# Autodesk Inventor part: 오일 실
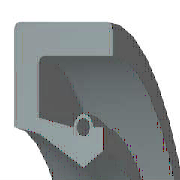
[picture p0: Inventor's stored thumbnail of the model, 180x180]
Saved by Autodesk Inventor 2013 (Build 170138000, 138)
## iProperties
IsCustomPart: 1
Created: 2015-10
Part Number: 오일 실
Material: 고무
Description: 오일-실
Document SubType Name: Modeling
Standard: KS B 2804
Designer: mdu
Standards Organization: KS
Language: ko-KR
Size Designation: S - 25 38 8
Categories: <MemberInstance><Categories><Category DisplayName="샤프트 부품" InternalName="7f7aeb1f-a693-4053-b835-cee3144e0d98" Mnemonic="SHFT"><Category DisplayName="실링" Intern
Density: 0.93 g/cm^3
Author: mdu
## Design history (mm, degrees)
revolve "본체" stored, may be unused: angle "d17" = 90 deg
revolve "스프링1" stored, may be unused: angle "d18" = 90 deg
body "Solid1"
sketch "스케치1"
  geometry: L1 (0, 19)-(8, 19); L2 (8, 19)-(8, 17.75); L3 (8, 17.75)-(1.75, 17.75); L4 (0, 19)-(0, 14.6); L5 (0, 14.6)-(1.75, 14.25); L6 (1.75, 14.25)-(4.9, 12.5); L7 (4.9, 12.5)-(0, 12.5); L8 (6.3, 13.375)-(6.3, 14.6); L9 (0, 0)-(9.586, 0) reference; L10 (4.9, 12.5)-(6.3, 13.375); L11 (0, 18)-(0, -3) reference; L12 (-1.917, 0)-(11.503, 0) reference; L13 (4.2, 14.6)-(1.75, 15.09); L14 (1.75, 15.09)-(1.75, 17.75); L15 (6.3, 14.6)-(5.6, 14.6); C1 r 0.455 at (4.9, 14.6); A1 r 0.7 centre (4.9, 14.6) between (5.6, 14.6) and (4.2, 14.6)
  constraints: 26 end point, 5 horizontal alignment, 4 perpendicular, 2 centre point, 2 collinear, 2 horizontal, 2 parallel, 2 point on circle, 2 point on line, 2 vertical alignment, 1 coincident
  dimensions: "d0" = 38 diameter of L1 L9 (= SD2); "d1" = 26.75 diameter of L8.start L9 (= ABDM); "d2" = 1.25 distance of L1.end L2.end (computed from SD); "d3" = 0.91 diameter of C1 (= SPDI); "d4" = 1.4 diameter of A1 (= SPDA); "d5" = 25 diameter of L6.end L9 (= NND); "d6" = 28.5 diameter of L5.end L9 (= TKDM); "d7" = 29.2 diameter of L4.end L9 (= HLDM); "d8" = 4.9 distance from line of C1.centre L4 (= SPDST); "d9" = 6.3 distance between parallel lines of L8 L4 (= SDI); "d10" = 8 distance between parallel lines of L2 L4 (= SWDT); "d12" = 1.75 distance between parallel lines of L14 L4 (= SD)
fillet "모깎기1" dims "d11" = 0.3 (= RR)
other parameters: "SD2" = 38 [user parameter; used in 1 equation term], "SWDT" = 8 [user parameter; used in 1 equation term], "RR" = 0.3 [user parameter; used in 1 equation term], "SD" = 1.75 [user parameter; used in 2 equation terms], "NND" = 25 [user parameter; used in 1 equation term], "SPDA" = 1.4 [user parameter; used in 1 equation term], "SPDI" = 0.91 [user parameter; used in 1 equation term], "TKDM" = 28.5 [user parameter; used in 1 equation term], "HLDM" = 29.2 [user parameter; used in 1 equation term], "ABDM" = 26.75 [user parameter; used in 1 equation term], "SDI" = 6.3 [user parameter; used in 1 equation term], "SPDST" = 4.9 [user parameter; used in 1 equation term], "d13" = 0, "d14" = 0, "d15" = 0, "LAB" = 0.35 [user parameter]
